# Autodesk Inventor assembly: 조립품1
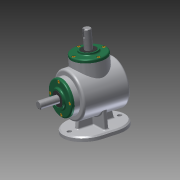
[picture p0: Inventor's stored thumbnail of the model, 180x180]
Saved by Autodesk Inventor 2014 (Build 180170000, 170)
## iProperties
Created: 2016-04
Part Number: 조립품1
Document SubType Name: Assembly
Designer: owner
Author: owner
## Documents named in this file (14)
- C:\Users\owner\Desktop\460407V1002\조립품1.iam
- C:\Users\owner\Desktop\460407V1002\답안.ipt
- C:\Users\owner\Desktop\460407V1002\커버.ipt
- C:\Users\owner\Desktop\460407V1002\베어링 6203.ipt
- C:\Users\owner\Desktop\460407V1002\메인 축.ipt
- 메인 축.ipt
- C:\Users\owner\Desktop\460407V1002\키 5x5.ipt
- C:\Users\owner\Desktop\460407V1002\메인 베벨기어.ipt
- C:\Users\owner\Desktop\460407V1002\서브 축.ipt
- 서브 축.ipt
- C:\Users\owner\Desktop\460407V1002\서브 베벨기어.ipt
- C:\Users\owner\Desktop\460407V1002\키 4x4.ipt
- C:\Users\owner\Desktop\460407V1002\오일실 17 32 8.ipt
- C:\Users\owner\Desktop\460407V1002\M4.ipt
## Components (8 placed, 1 different names)
1. M4:1
2. M4:3
3. M4:4
4. M4:5
5. M4:2
6. M4:6
7. M4:7
8. M4:8
